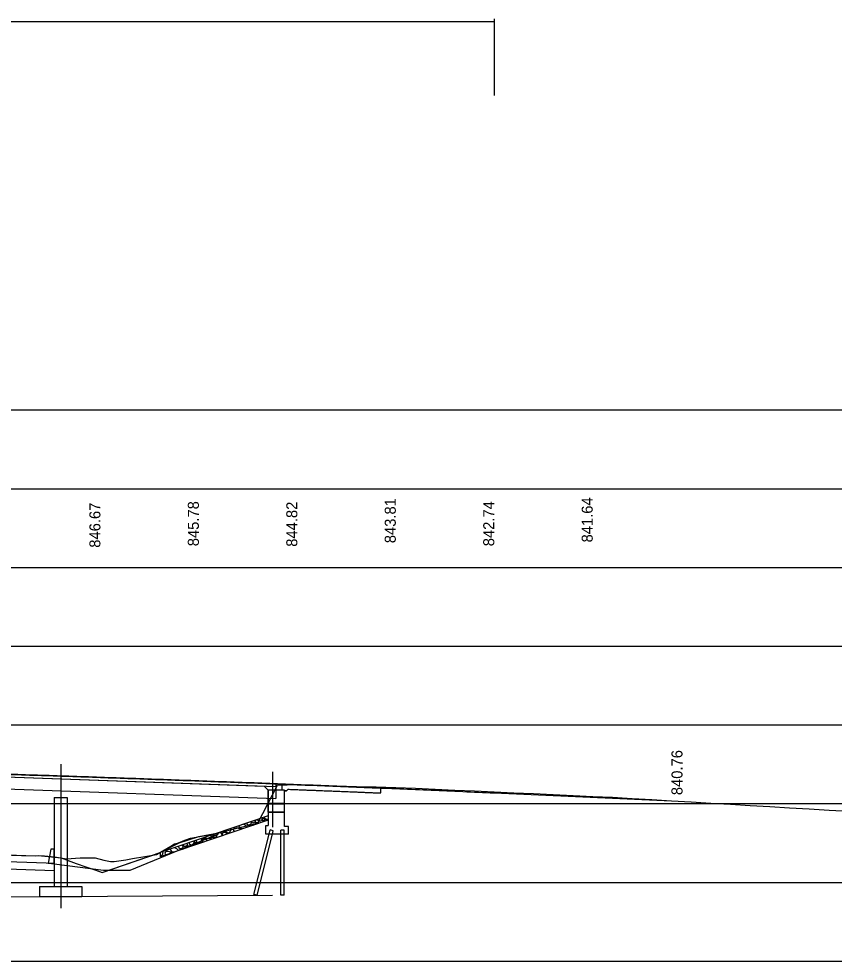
# Model space of a CAD drawing. Extents: x -434 to 1339, y -871 to 603.
# Drawn here: x 579.3 to 786.3, y -500 to -260.7 of the extents above; entities that cross this region are included whole.
import ezdxf

# ---------------------------------------------------------------- set-up
doc = ezdxf.new("R2010")
doc.units = 0
for name, color, linetype in [('BR_P_Brg_Pad_Object', 7, 'Continuous'), ('BR_P_Gen_Approach_Slab', 7, 'Continuous'), ('BR_P_Gen_Hatch', 7, 'Continuous'), ('BR_P_Gen_Slope_Protection', 7, 'Continuous'), ('BR_P_Slab_Object', 7, 'Continuous'), ('BR_P_Sub_Const_Joint', 7, 'Continuous'), ('BR_P_Sub_Object', 7, 'Continuous'), ('BR_X_Beam_Object', 7, 'Continuous'), ('BR_X_Sub_Centerline', 7, 'Continuous'), ('BR_X_Sub_Deep_Hidden', 7, 'Continuous'), ('BR_X_Sub_Deep_Object', 7, 'Continuous'), ('BR_X_Sub_Object', 7, 'Continuous'), ('GK_Cells', 7, 'Continuous'), ('PF_P_Grade_Line', 7, 'Continuous'), ('PF_P_Text', 7, 'Continuous'), ('PF_X_Ground_Line', 7, 'Continuous'), ('SC_Scratch1', 7, 'Continuous'), ('SC_Scratch2', 7, 'Continuous'), ('XS_P_Barrier_Surface', 7, 'Continuous'), ('XS_P_Ditch_Bottom', 7, 'Continuous'), ('XS_P_Finished_Grade', 7, 'Continuous'), ('XS_P_Finished_Grade_Seeded', 7, 'Continuous'), ('XS_P_Shoulder_Surface', 7, 'Continuous'), ('XS_P_Subgrade', 7, 'Continuous'), ('XS_X_Ground_Line', 7, 'Continuous')]:
    doc.layers.add(name, color=color, linetype=linetype)

msp = doc.modelspace()

# ---------------------------------------------------------------- linework, layer by layer
at = {"layer": 'BR_P_Brg_Pad_Object'}
msp.add_lwpolyline([(643.2, -459.95), (644.2, -459.95), (644.2, -460.12), (643.2, -460.12)], close=True, dxfattribs=at)
at = {"layer": 'BR_P_Gen_Approach_Slab'}
for p, q in [((647.24, -456.74), (646.74, -456.74)), ((647.24, -456.74), (647.64, -456.34)), ((671.19, -457.29), (671.19, -456.03))]:
    msp.add_line(p, q, dxfattribs=at)
msp.add_open_spline([(647.64, -456.34), (655.49, -456.65), (663.34, -456.96), (671.19, -457.29)], degree=2, dxfattribs=at)
at = {"layer": 'BR_P_Gen_Hatch'}
for p, q in [((641.6, -455.57), (642.6, -456.53)), ((642.6, -456.53), (642.6, -462.12)), ((646.74, -462.12), (646.74, -456.74)), ((646.74, -456.74), (647.24, -456.74)), ((647.24, -456.74), (647.64, -456.34)), ((671.19, -457.29), (671.19, -456.03)), ((642.6, -462.12), (646.74, -462.12))]:
    msp.add_line(p, q, dxfattribs=at)
for points in [[(340.09, -448.44), (425.16, -449.49), (499.17, -451.07), (573.52, -453.13), (641.6, -455.57)], [(639.31, -464.21), (639.36, -464.26), (639.32, -464.62), (638.99, -464.91), (638.7, -464.92), (638.41, -464.72)], [(641.15, -463.58), (640.97, -464.12), (640.62, -464.48), (640.28, -464.54), (639.97, -464.27), (639.91, -464.01)], [(641.17, -464.27), (641.12, -463.98), (641.3, -463.78), (641.57, -463.79), (641.74, -464), (641.72, -464.21), (641.52, -464.38), (641.35, -464.39), (641.17, -464.27)], [(642.6, -463.82), (642.43, -463.99), (642.09, -464.05), (641.78, -463.79), (641.7, -463.4)], [(633.13, -466.32), (633.15, -466.48), (632.96, -467.05), (632.61, -467.41), (632.26, -467.47), (631.96, -467.2), (631.87, -466.78), (631.87, -466.75)], [(634.07, -467.06), (633.84, -466.84), (633.78, -466.49), (634.05, -466.19), (634.47, -466.1), (634.8, -466.14)], [(634.78, -466.13), (635.3, -466.35), (635.48, -466.57)], [(636.08, -466.37), (635.56, -466.19), (635.2, -465.84), (635.16, -465.63)], [(636.34, -465.22), (636.65, -465.36), (636.96, -465.73), (636.97, -466.05), (636.94, -466.08)], [(637.29, -465.28), (637.23, -464.92)], [(638.08, -464.63), (638.24, -464.82), (638.21, -465.18), (637.87, -465.47), (637.58, -465.47), (637.29, -465.28)], [(638.14, -465.67), (638.26, -465.52), (638.68, -465.43), (638.79, -465.45)], [(638.41, -464.72), (638.37, -464.53)], [(639.37, -465.25), (639.34, -465.08), (639.64, -464.74), (640.08, -464.75), (640.24, -464.95)], [(641.14, -464.64), (641.24, -464.53), (641.45, -464.54)], [(625.63, -468.88), (625.66, -469.06), (625.47, -469.63), (625.12, -470), (624.77, -470.05), (624.47, -469.79), (624.38, -469.37), (624.38, -469.3)], [(625.97, -469.65), (625.88, -469.17), (626.18, -468.83), (626.63, -468.84), (626.92, -469.19), (626.89, -469.51)], [(627.97, -468.08), (628.15, -468.29), (628.16, -468.6), (627.87, -468.87), (627.31, -468.94), (626.75, -468.75), (626.55, -468.56)], [(627.89, -469.16), (628.03, -468.84), (628.4, -468.53), (628.72, -468.52), (628.98, -468.79)], [(628.89, -467.77), (628.6, -468.02), (628.31, -468.02), (628.26, -467.98)], [(628.86, -468.48), (628.81, -468.19), (628.99, -467.99), (629.26, -468), (629.43, -468.21), (629.41, -468.42), (629.21, -468.6), (629.03, -468.6), (628.86, -468.48)], [(629.58, -468.59), (629.56, -468.5), (629.59, -468.16)], [(629.59, -468.19), (629.81, -467.67), (630.18, -467.36), (630.5, -467.35), (630.77, -467.63), (630.83, -468.16)], [(631.65, -466.83), (631.64, -466.88), (631.31, -467.17), (631.02, -467.17), (630.89, -467.08)], [(631.1, -468.07), (631.02, -467.62), (631.31, -467.28), (631.76, -467.29), (632.05, -467.64), (632.04, -467.75)], [(618.9, -471.18), (619.33, -471.36), (619.65, -471.73), (619.65, -471.98)], [(619.97, -471.28), (619.9, -470.84)], [(620.71, -470.56), (620.92, -470.82), (620.89, -471.18), (620.55, -471.47), (620.27, -471.48), (619.97, -471.28)], [(621.09, -470.72), (621.04, -470.44)], [(621.93, -470.14), (622.04, -470.27), (622.01, -470.63), (621.67, -470.91), (621.38, -470.92), (621.09, -470.72)], [(622.03, -471.16), (622.02, -471.08), (622.32, -470.75), (622.77, -470.75), (622.87, -470.88)], [(623.84, -469.49), (623.84, -469.55), (623.65, -470.12), (623.3, -470.48), (622.96, -470.54), (622.66, -470.28), (622.58, -469.92)], [(623.86, -470.27), (623.81, -469.98), (623.98, -469.78), (624.25, -469.79), (624.43, -470), (624.41, -470.21), (624.2, -470.39), (624.03, -470.39), (623.86, -470.27)], [(625.46, -469.99), (625.62, -469.81), (625.98, -469.82)], [(626.14, -469.76), (625.97, -469.65)], [(615.8, -472.23), (615.83, -472.48), (615.64, -473.05), (615.29, -473.41), (615.19, -473.43)], [(616.68, -472.99), (616.53, -472.84), (616.47, -472.5), (616.73, -472.19), (617.15, -472.1), (617.49, -472.14)], [(616.94, -471.85), (616.83, -471.94), (616.66, -471.94)], [(617.46, -472.13), (617.98, -472.36), (618.1, -472.5)], [(618.63, -472.33), (618.24, -472.2), (617.88, -471.85), (617.83, -471.54)], [(620.94, -471.54), (620.95, -471.53), (621, -471.52)]]:
    msp.add_lwpolyline(points, dxfattribs=at)
msp.add_spline([(671.19, -456.03), (668, -455.9), (660, -455.58), (652, -455.26), (644, -454.94), (636, -454.64), (628, -454.34), (620, -454.04), (612, -453.75), (604, -453.47), (596, -453.19), (588, -452.92), (580, -452.66), (572, -452.4), (564, -452.15), (556, -451.9), (548, -451.66), (540, -451.42), (532, -451.19), (524, -450.97), (516, -450.76), (508, -450.54), (500, -450.34), (492, -450.14), (484, -449.95), (476, -449.76), (468, -449.58), (460, -449.41), (452, -449.24), (444, -449.08), (436, -448.92), (428, -448.77), (420, -448.62), (412, -448.49), (404, -448.35), (396, -448.23), (388, -448.11), (380, -447.99), (372, -447.88), (364, -447.78), (356, -447.69), (348, -447.6), (340, -447.51), (332, -447.43), (324, -447.36), (316, -447.29), (310.5, -447.25)], degree=3, dxfattribs=at)
msp.add_open_spline([(647.64, -456.34), (655.49, -456.65), (663.34, -456.96), (671.19, -457.29)], degree=2, dxfattribs=at)
at = {"layer": 'BR_P_Gen_Slope_Protection'}
for p, q in [((642.6, -463.09), (615.19, -472.44)), ((642.6, -464.15), (615.19, -473.5)), ((615.19, -472.44), (615.19, -473.5))]:
    msp.add_line(p, q, dxfattribs=at)
at = {"layer": 'BR_P_Slab_Object'}
msp.add_lwpolyline([(340.09, -448.44), (425.16, -449.49), (499.17, -451.07), (573.52, -453.13), (641.6, -455.57)], dxfattribs=at)
at = {"layer": 'BR_P_Sub_Const_Joint'}
msp.add_lwpolyline([(646.19, -456.53), (642.6, -456.53)], dxfattribs=at)
at = {"layer": 'BR_P_Sub_Object'}
for p, q in [((642.6, -456.53), (641.6, -455.57)), ((642.6, -459.95), (642.6, -456.53)), ((646.19, -456.53), (646.19, -455.03)), ((646.74, -456.53), (646.19, -456.53)), ((646.74, -459.95), (646.74, -456.53)), ((646.74, -459.95), (642.6, -459.95)), ((646.74, -460.12), (642.6, -460.12)), ((642.6, -462.12), (642.6, -460.12)), ((646.74, -462.12), (646.74, -460.12)), ((646.74, -462.12), (642.6, -462.12))]:
    msp.add_line(p, q, dxfattribs=at)
at = {"layer": 'BR_X_Beam_Object'}
msp.add_line((644.55, -454.94), (644.55, -458.66), dxfattribs=at)
for points in [[(337.13, -448.4), (425.16, -449.49), (499.17, -451.07), (573.52, -453.13), (644.55, -455.67)], [(337.13, -451.39), (425.11, -452.48), (499.1, -454.06), (573.42, -456.12), (644.55, -458.66)]]:
    msp.add_lwpolyline(points, dxfattribs=at)
at = {"layer": 'BR_X_Sub_Centerline'}
for p, q in [((589.91, -449.98), (589.91, -486.58)), ((643.7, -451.93), (643.7, -465.99))]:
    msp.add_line(p, q, dxfattribs=at)
at = {"layer": 'BR_X_Sub_Deep_Hidden'}
for p, q in [((642.81, -467.77), (643.08, -466.67)), ((643.89, -466.87), (643.08, -466.67)), ((643.67, -467.77), (643.89, -466.87)), ((646.65, -466.77), (645.82, -466.77)), ((645.82, -467.77), (645.82, -466.77)), ((646.65, -467.77), (646.65, -466.77))]:
    msp.add_line(p, q, dxfattribs=at)
at = {"layer": 'BR_X_Sub_Deep_Object'}
for p, q in [((638.98, -483.08), (642.81, -467.77)), ((639.79, -483.28), (643.67, -467.77)), ((645.82, -483.28), (645.82, -467.77)), ((646.65, -483.28), (646.65, -467.77)), ((639.79, -483.28), (638.98, -483.08)), ((646.65, -483.28), (645.82, -483.28))]:
    msp.add_line(p, q, dxfattribs=at)
at = {"layer": 'BR_X_Sub_Object'}
for p, q in [((588.25, -458.45), (591.56, -458.45)), ((588.25, -458.45), (588.25, -481.08)), ((591.56, -458.45), (591.56, -481.08)), ((642.6, -462.12), (642.6, -465.52)), ((646.74, -465.77), (646.74, -462.12)), ((641.99, -467.77), (641.99, -465.52)), ((641.99, -465.52), (642.6, -465.52)), ((647.74, -465.77), (646.74, -465.77)), ((647.74, -467.77), (647.74, -465.77)), ((647.74, -467.77), (641.99, -467.77)), ((584.5, -481.08), (595.31, -481.08)), ((584.5, -481.08), (584.5, -483.58)), ((595.31, -481.08), (595.31, -483.58)), ((584.5, -483.58), (595.31, -483.58))]:
    msp.add_line(p, q, dxfattribs=at)
at = {"layer": 'GK_Cells'}
msp.add_line((0, -500), (1100, -500), dxfattribs=at)
at = {"layer": 'PF_P_Grade_Line'}
msp.add_line((700, -457.26), (745, -459.24), dxfattribs=at)
msp.add_spline([(300, -447.18), (308, -447.23), (316, -447.29), (324, -447.36), (332, -447.43), (340, -447.51), (348, -447.6), (356, -447.69), (364, -447.78), (372, -447.88), (380, -447.99), (388, -448.11), (396, -448.23), (404, -448.35), (412, -448.49), (420, -448.62), (428, -448.77), (436, -448.92), (444, -449.08), (452, -449.24), (460, -449.41), (468, -449.58), (476, -449.76), (484, -449.95), (492, -450.14), (500, -450.34), (508, -450.54), (516, -450.76), (524, -450.97), (532, -451.19), (540, -451.42), (548, -451.66), (556, -451.9), (564, -452.15), (572, -452.4), (580, -452.66), (588, -452.92), (596, -453.19), (604, -453.47), (612, -453.75), (620, -454.04), (628, -454.34), (636, -454.64), (644, -454.94), (652, -455.26), (660, -455.58), (668, -455.9), (676, -456.23), (684, -456.57), (692, -456.91), (700, -457.26)], degree=3, dxfattribs=at)
at = {"layer": 'PF_P_Text'}
for p, q in [((700, -260.67), (700, -280.17)), ((300, -261.37), (700, -261.37))]:
    msp.add_line(p, q, dxfattribs=at)
at = {"layer": 'PF_X_Ground_Line'}
msp.add_lwpolyline([(336.84, -447.65), (425.17, -448.74), (499.19, -450.32), (573.54, -452.38), (645.15, -454.94)], dxfattribs=at)
at = {"layer": 'SC_Scratch1'}
for p, q in [((0, -360), (1339.17, -360)), ((0, -380), (1339.17, -380)), ((0, -400), (1339.17, -400)), ((0, -420), (1339.17, -420)), ((0, -440), (1339.17, -440)), ((0, -460), (1339.17, -460)), ((0, -480), (1339.17, -480)), ((499.95, -484.08), (643.7, -483.28)), ((0, -500), (1339.17, -500))]:
    msp.add_line(p, q, dxfattribs=at)
at = {"layer": 'SC_Scratch2'}
msp.add_line((588.21, -471.54), (588.25, -471.58), dxfattribs=at)
for points in [[(575, -473), (580, -473.16), (585, -473.23), (590, -473.79), (593.84, -475.21), (596.27, -476.04), (598.88, -476.93), (600.45, -477.47), (615, -472.48), (620, -469.92), (625, -468.32), (630, -467.41), (635, -466.18), (640, -464.96), (645, -455.3), (650, -455.15), (655, -455.3), (660, -455.45), (665, -455.6), (670, -455.76), (675, -455.91), (680, -456.07), (685, -456.31), (690, -456.54), (695, -456.77), (700, -457), (705, -457.23), (710, -457.46), (715, -457.7), (720, -457.93), (725, -458.16), (730, -458.39), (735, -458.67), (740, -458.97), (745, -459.26), (750, -459.56), (755, -459.85), (760, -460.14), (765, -460.44), (770, -460.73), (775, -461.02), (780, -461.32), (785, -461.61), (790, -461.94)], [(591.56, -474.37), (593.84, -475.21), (596.27, -476.04), (598.88, -476.93), (600.45, -477.47), (615.19, -472.42)]]:
    msp.add_lwpolyline(points, dxfattribs=at)
at = {"layer": 'XS_P_Barrier_Surface'}
for p, q in [((587.41, -471.58), (586.75, -475.09)), ((587.46, -471.54), (587.41, -471.58)), ((588.21, -471.54), (587.46, -471.54)), ((588.21, -471.54), (587.46, -471.54)), ((588.25, -475.09), (588.25, -471.58)), ((586.75, -475.09), (588.25, -475.09))]:
    msp.add_line(p, q, dxfattribs=at)
at = {"layer": 'XS_P_Ditch_Bottom'}
msp.add_line((600.81, -476.86), (607.53, -476.86), dxfattribs=at)
at = {"layer": 'XS_P_Finished_Grade'}
for p, q in [((607.53, -476.86), (630.01, -467.63)), ((588.22, -475.32), (600.81, -476.86))]:
    msp.add_line(p, q, dxfattribs=at)
at = {"layer": 'XS_P_Finished_Grade_Seeded'}
msp.add_line((586.19, -475.01), (588.22, -475.32), dxfattribs=at)
at = {"layer": 'XS_P_Shoulder_Surface'}
msp.add_line((572.91, -474.53), (586.19, -475.01), dxfattribs=at)
at = {"layer": 'XS_P_Subgrade'}
for p in [(588.22, -475.32), (572.91, -476.41)]:
    msp.add_line(p, (588.22, -476.96), dxfattribs=at)
at = {"layer": 'XS_X_Ground_Line'}
for p, q in [((621.46, -469.26), (622.84, -468.74)), ((622.84, -468.74), (629, -467.64)), ((629, -467.64), (630.01, -467.4)), ((614.27, -472.9), (617.85, -470.8)), ((617.85, -470.8), (618.82, -470.23)), ((618.82, -470.23), (619.79, -469.98)), ((619.79, -469.98), (621.46, -469.26)), ((572.45, -472.9), (583.54, -473.26)), ((583.54, -473.26), (584.27, -473.17)), ((584.27, -473.17), (585.26, -473.24)), ((585.26, -473.24), (585.82, -473.29)), ((585.82, -473.29), (588.31, -473.51)), ((588.31, -473.51), (591.43, -474.03)), ((591.43, -474.03), (594.86, -473.76)), ((594.86, -473.76), (598.65, -473.72)), ((598.65, -473.72), (600.88, -474.36)), ((608.15, -473.93), (611.28, -473.39)), ((611.28, -473.39), (614.27, -472.9)), ((600.88, -474.36), (602.54, -474.69)), ((602.54, -474.69), (603.5, -474.72)), ((603.5, -474.72), (606.47, -474.3)), ((606.47, -474.3), (608.15, -473.93))]:
    msp.add_line(p, q, dxfattribs=at)

# ---------------------------------------------------------------- texts
at = {"layer": 'PF_P_Text'}
for s, p in [('843.81', (675, -393.85)), ('841.64', (725, -393.65)), ('846.67', (600, -395)), ('845.78', (625, -394.62)), ('844.82', (650, -394.75)), ('842.74', (700, -394.62)), ('840.76', (747.8, -457.84))]:
    msp.add_text(s, height=2.8, rotation=90, dxfattribs=at).set_placement(p)

doc.saveas('drawing.dxf')
